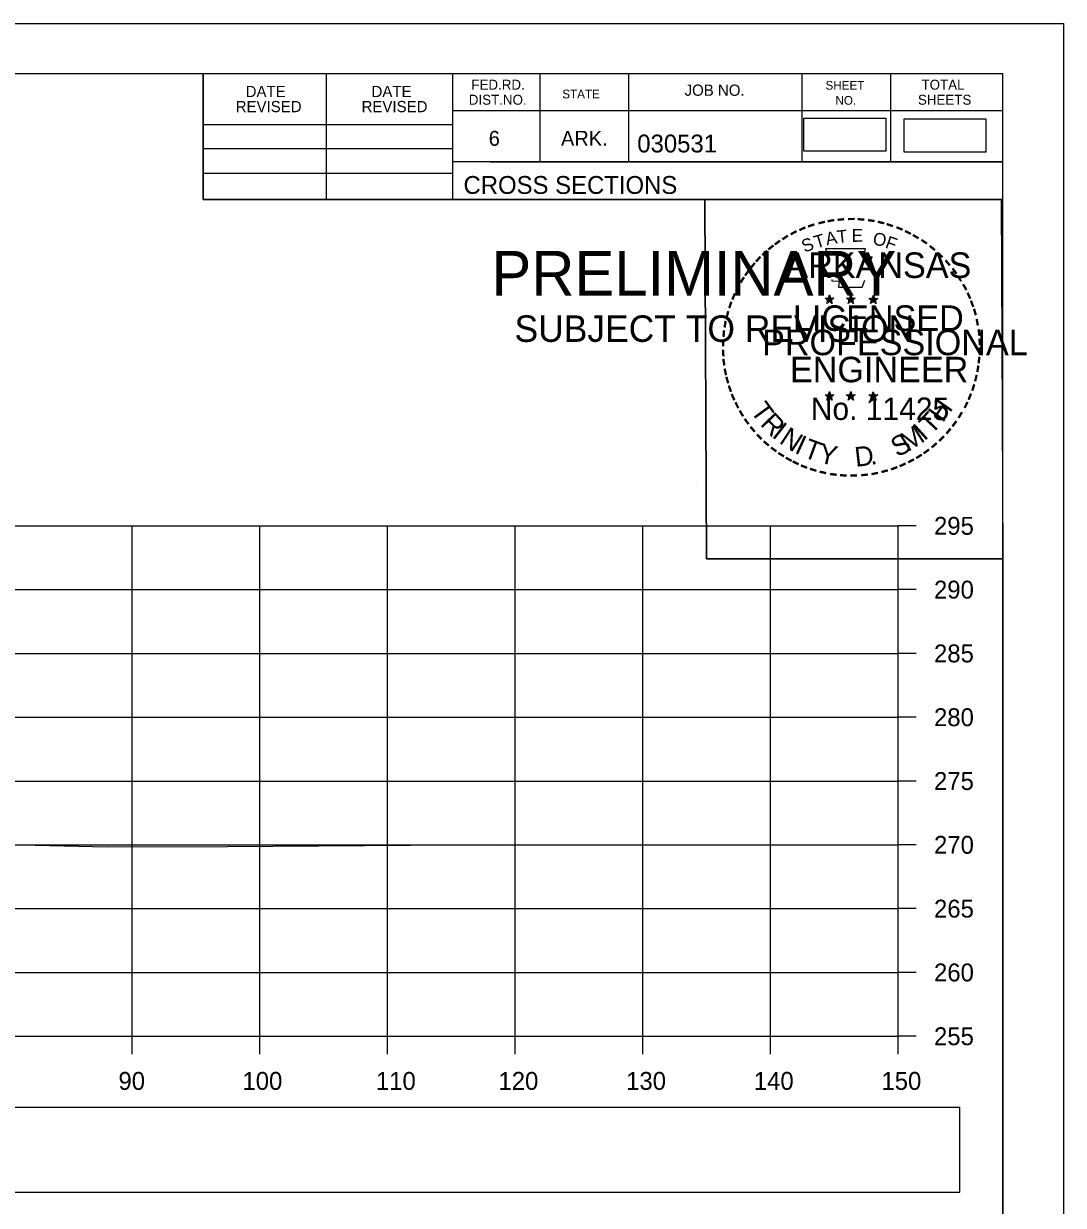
# Model space of a CAD drawing. Extents: x 285 to 4233, y -659 to 3710.
# Drawn here: x 2641 to 2722.4, y 1163.6 to 1256.2 of the extents above; entities that cross this region are included whole.
import ezdxf

# ---------------------------------------------------------------- set-up
doc = ezdxf.new("R2010")
doc.units = 0
for name, color, linetype in [('R_Axis', 7, 'Continuous'), ('R_Axis Annot', 7, 'Continuous'), ('R_Border', 7, 'Continuous'), ('R_Border PE', 7, 'Continuous'), ('R_Border Prem', 7, 'Continuous'), ('R_Exist Surface', 7, 'Continuous'), ('R_Grid', 7, 'Continuous'), ('R_No Plot', 7, 'Continuous')]:
    doc.layers.add(name, color=color, linetype=linetype)

msp = doc.modelspace()

# ---------------------------------------------------------------- linework, layer by layer
at = {"layer": 'R_Axis'}
for p, q in [((2709.501, 1176.842), (2709.501, 1216.842)), ((2710.901, 1216.842), (2709.501, 1216.842)), ((2710.901, 1211.842), (2709.501, 1211.842)), ((2710.901, 1206.842), (2709.501, 1206.842)), ((2710.901, 1201.842), (2709.501, 1201.842)), ((2710.901, 1196.842), (2709.501, 1196.842)), ((2710.901, 1191.842), (2709.501, 1191.842)), ((2710.901, 1186.842), (2709.501, 1186.842)), ((2710.901, 1181.842), (2709.501, 1181.842)), ((2409.501, 1176.842), (2709.501, 1176.842)), ((2649.501, 1175.442), (2649.501, 1176.842)), ((2659.501, 1175.442), (2659.501, 1176.842)), ((2669.501, 1175.442), (2669.501, 1176.842)), ((2679.501, 1175.442), (2679.501, 1176.842)), ((2689.501, 1175.442), (2689.501, 1176.842)), ((2699.501, 1175.442), (2699.501, 1176.842)), ((2709.501, 1175.442), (2709.501, 1176.842)), ((2710.901, 1176.842), (2709.501, 1176.842))]:
    msp.add_line(p, q, dxfattribs=at)
at = {"layer": 'R_Axis Annot'}
for points in [[(2702.085, 1246.216), (2708.544, 1246.216), (2708.544, 1248.774), (2702.085, 1248.774)], [(2709.939, 1246.155), (2716.397, 1246.155), (2716.397, 1248.713), (2709.939, 1248.713)], [(2573.959, 1164.614), (2714.324, 1164.614), (2714.324, 1171.266), (2573.959, 1171.266)]]:
    msp.add_lwpolyline(points, close=True, dxfattribs=at)
at = {"layer": 'R_Border'}
for p, q in [((2401.501, 1252.302), (2717.681, 1252.302)), ((2655.041, 1242.422), (2655.041, 1252.302)), ((2664.721, 1242.422), (2664.721, 1252.302)), ((2674.581, 1252.302), (2674.581, 1242.422)), ((2681.421, 1252.302), (2681.421, 1245.362)), ((2688.361, 1252.302), (2688.361, 1245.362)), ((2701.941, 1252.302), (2701.941, 1245.362)), ((2708.881, 1252.302), (2708.881, 1245.362)), ((2717.681, 1046.842), (2717.681, 1252.302)), ((2717.681, 1249.362), (2674.581, 1249.362)), ((2717.681, 1249.382), (2717.681, 1249.382)), ((2655.041, 1248.282), (2674.581, 1248.282)), ((2655.041, 1246.422), (2674.581, 1246.422)), ((2717.681, 1245.362), (2674.581, 1245.362)), ((2677.541, 1245.362), (2717.681, 1245.362)), ((2655.041, 1244.482), (2674.581, 1244.482)), ((2717.681, 1242.422), (2655.041, 1242.422))]:
    msp.add_line(p, q, dxfattribs=at)
at = {"layer": 'R_Border PE'}
for p, q in [((2703.766, 1234.678), (2704.115, 1234.567)), ((2703.766, 1234.678), (2704.019, 1234.633)), ((2703.766, 1234.678), (2704.003, 1234.556)), ((2703.899, 1234.27), (2704.115, 1234.567)), ((2703.899, 1234.27), (2704.025, 1234.514)), ((2703.899, 1234.27), (2704.113, 1234.487)), ((2704.115, 1234.932), (2704.074, 1234.68)), ((2704.328, 1234.27), (2704.113, 1234.484)), ((2704.115, 1234.567), (2704.115, 1234.932)), ((2704.115, 1234.932), (2704.164, 1234.682)), ((2704.462, 1234.678), (2704.115, 1234.567)), ((2704.328, 1234.27), (2704.115, 1234.567)), ((2704.462, 1234.678), (2704.176, 1234.629)), ((2704.328, 1234.27), (2704.191, 1234.561)), ((2704.462, 1234.678), (2704.258, 1234.576)), ((2705.436, 1234.678), (2705.785, 1234.567)), ((2705.436, 1234.678), (2705.689, 1234.633)), ((2705.436, 1234.678), (2705.673, 1234.556)), ((2705.569, 1234.27), (2705.785, 1234.567)), ((2705.569, 1234.27), (2705.695, 1234.514)), ((2705.569, 1234.27), (2705.783, 1234.487)), ((2705.785, 1234.932), (2705.744, 1234.68)), ((2705.998, 1234.27), (2705.783, 1234.484)), ((2705.785, 1234.567), (2705.785, 1234.932)), ((2705.785, 1234.932), (2705.834, 1234.682)), ((2706.132, 1234.678), (2705.785, 1234.567)), ((2705.998, 1234.27), (2705.785, 1234.567)), ((2706.132, 1234.678), (2705.846, 1234.629)), ((2705.998, 1234.27), (2705.861, 1234.561)), ((2706.132, 1234.678), (2705.928, 1234.576)), ((2707.2, 1234.666), (2707.549, 1234.555)), ((2707.2, 1234.666), (2707.453, 1234.621)), ((2707.2, 1234.666), (2707.437, 1234.544)), ((2707.333, 1234.258), (2707.549, 1234.555)), ((2707.333, 1234.258), (2707.459, 1234.502)), ((2707.333, 1234.258), (2707.547, 1234.475)), ((2707.549, 1234.92), (2707.508, 1234.668)), ((2707.549, 1234.555), (2707.549, 1234.92)), ((2707.549, 1234.92), (2707.598, 1234.67)), ((2707.896, 1234.666), (2707.549, 1234.555)), ((2707.762, 1234.258), (2707.549, 1234.555)), ((2707.896, 1234.666), (2707.61, 1234.617)), ((2707.762, 1234.258), (2707.625, 1234.549)), ((2707.896, 1234.666), (2707.692, 1234.564)), ((2707.762, 1234.258), (2707.547, 1234.472)), ((2703.762, 1227.105), (2704.111, 1226.994)), ((2703.762, 1227.105), (2704.015, 1227.06)), ((2703.762, 1227.105), (2703.999, 1226.983)), ((2704.111, 1227.359), (2704.07, 1227.107)), ((2704.111, 1226.994), (2704.111, 1227.359)), ((2704.111, 1227.359), (2704.16, 1227.109)), ((2704.458, 1227.105), (2704.111, 1226.994)), ((2704.458, 1227.105), (2704.172, 1227.056)), ((2704.458, 1227.105), (2704.254, 1227.003)), ((2705.431, 1227.105), (2705.78, 1226.994)), ((2705.431, 1227.105), (2705.684, 1227.06)), ((2705.431, 1227.105), (2705.668, 1226.983)), ((2705.78, 1227.359), (2705.739, 1227.107)), ((2705.78, 1226.994), (2705.78, 1227.359)), ((2705.78, 1227.359), (2705.829, 1227.109)), ((2706.127, 1227.105), (2705.78, 1226.994)), ((2706.127, 1227.105), (2705.841, 1227.056)), ((2706.127, 1227.105), (2705.923, 1227.003)), ((2707.198, 1227.095), (2707.547, 1226.984)), ((2707.198, 1227.095), (2707.451, 1227.05)), ((2707.198, 1227.095), (2707.435, 1226.973)), ((2707.547, 1227.349), (2707.506, 1227.097)), ((2707.547, 1226.984), (2707.547, 1227.349)), ((2707.547, 1227.349), (2707.596, 1227.099)), ((2707.894, 1227.095), (2707.547, 1226.984)), ((2707.894, 1227.095), (2707.608, 1227.046)), ((2707.894, 1227.095), (2707.69, 1226.993)), ((2703.895, 1226.697), (2704.111, 1226.994)), ((2703.895, 1226.697), (2704.021, 1226.941)), ((2703.895, 1226.697), (2704.109, 1226.914)), ((2704.324, 1226.697), (2704.109, 1226.911)), ((2704.324, 1226.697), (2704.111, 1226.994)), ((2704.324, 1226.697), (2704.187, 1226.988)), ((2705.564, 1226.697), (2705.78, 1226.994)), ((2705.564, 1226.697), (2705.69, 1226.941)), ((2705.564, 1226.697), (2705.778, 1226.914)), ((2705.993, 1226.697), (2705.778, 1226.911)), ((2705.993, 1226.697), (2705.78, 1226.994)), ((2705.993, 1226.697), (2705.856, 1226.988)), ((2707.331, 1226.687), (2707.547, 1226.984)), ((2707.331, 1226.687), (2707.457, 1226.931)), ((2707.331, 1226.687), (2707.545, 1226.904)), ((2707.76, 1226.687), (2707.545, 1226.901)), ((2707.76, 1226.687), (2707.547, 1226.984)), ((2707.76, 1226.687), (2707.623, 1226.978))]:
    msp.add_line(p, q, dxfattribs=at)
for points in [[(2703.807, 1238.556), (2704.076, 1237.729)], [(2707.318, 1237.634), (2707.46, 1237.918), (2706.775, 1237.894), (2706.923, 1238.556), (2703.807, 1238.556)], [(2704.299, 1236.133), (2704.299, 1236.046), (2704.862, 1236.027), (2704.808, 1235.554), (2706.678, 1235.554), (2706.879, 1236.09)], [(2704.115, 1234.932), (2704.328, 1234.27), (2703.766, 1234.678), (2704.462, 1234.678), (2703.899, 1234.27), (2704.115, 1234.932)], [(2705.785, 1234.932), (2705.998, 1234.27), (2705.436, 1234.678), (2706.132, 1234.678), (2705.569, 1234.27), (2705.785, 1234.932)], [(2707.549, 1234.92), (2707.762, 1234.258), (2707.2, 1234.666), (2707.896, 1234.666), (2707.333, 1234.258), (2707.549, 1234.92)], [(2704.111, 1227.359), (2704.324, 1226.697), (2703.762, 1227.105), (2704.458, 1227.105), (2703.895, 1226.697), (2704.111, 1227.359)], [(2705.78, 1227.359), (2705.993, 1226.697), (2705.431, 1227.105), (2706.127, 1227.105), (2705.564, 1226.697), (2705.78, 1227.359)], [(2707.547, 1227.349), (2707.76, 1226.687), (2707.198, 1227.095), (2707.894, 1227.095), (2707.331, 1226.687), (2707.547, 1227.349)]]:
    msp.add_lwpolyline(points, dxfattribs=at)
for centre, radius in [((2704.114, 1234.566), 0.172), ((2704.114, 1234.566), 0.145), ((2704.114, 1234.566), 0.116), ((2704.114, 1234.566), 0.0991), ((2704.114, 1234.566), 0.0747), ((2704.114, 1234.566), 0.0495), ((2704.114, 1234.566), 0.0296), ((2705.784, 1234.566), 0.172), ((2705.784, 1234.566), 0.145), ((2705.784, 1234.566), 0.116), ((2705.784, 1234.566), 0.0991), ((2705.784, 1234.566), 0.0747), ((2705.784, 1234.566), 0.0495), ((2705.784, 1234.566), 0.0296), ((2707.548, 1234.554), 0.172), ((2707.548, 1234.554), 0.145), ((2707.548, 1234.554), 0.116), ((2707.548, 1234.554), 0.0991), ((2707.548, 1234.554), 0.0747), ((2707.548, 1234.554), 0.0495), ((2707.548, 1234.554), 0.0296), ((2704.11, 1226.993), 0.172), ((2704.11, 1226.993), 0.145), ((2704.11, 1226.993), 0.116), ((2704.11, 1226.993), 0.0991), ((2704.11, 1226.993), 0.0747), ((2705.779, 1226.993), 0.172), ((2705.779, 1226.993), 0.145), ((2705.779, 1226.993), 0.116), ((2705.779, 1226.993), 0.0991), ((2705.779, 1226.993), 0.0747), ((2707.546, 1226.983), 0.172), ((2707.546, 1226.983), 0.145), ((2707.546, 1226.983), 0.116), ((2707.546, 1226.983), 0.0991), ((2704.11, 1226.993), 0.0495), ((2704.11, 1226.993), 0.0296), ((2705.779, 1226.993), 0.0495), ((2705.779, 1226.993), 0.0296), ((2707.546, 1226.983), 0.0747), ((2707.546, 1226.983), 0.0495), ((2707.546, 1226.983), 0.0296)]:
    msp.add_circle(centre, radius, dxfattribs=at)
at = {"layer": 'R_Exist Surface'}
msp.add_lwpolyline([(2635.101, 1191.968), (2647.54, 1191.68), (2656.942, 1191.711), (2678.485, 1191.857), (2689.528, 1191.849), (2698.624, 1191.843), (2709.501, 1191.857)], dxfattribs=at)
at = {"layer": 'R_Grid'}
for p, q in [((2409.501, 1216.842), (2709.501, 1216.842)), ((2649.501, 1176.842), (2649.501, 1216.842)), ((2659.501, 1176.842), (2659.501, 1216.842)), ((2669.501, 1176.842), (2669.501, 1216.842)), ((2679.501, 1176.842), (2679.501, 1216.842)), ((2689.501, 1176.842), (2689.501, 1216.842)), ((2699.501, 1176.842), (2699.501, 1216.842)), ((2709.501, 1176.842), (2709.501, 1216.842)), ((2409.501, 1211.842), (2709.501, 1211.842)), ((2409.501, 1206.842), (2709.501, 1206.842)), ((2409.501, 1201.842), (2709.501, 1201.842)), ((2409.501, 1196.842), (2709.501, 1196.842)), ((2409.501, 1191.842), (2709.501, 1191.842)), ((2409.501, 1186.842), (2709.501, 1186.842)), ((2409.501, 1181.842), (2709.501, 1181.842)), ((2409.501, 1176.842), (2709.501, 1176.842))]:
    msp.add_line(p, q, dxfattribs=at)
at = {"layer": 'R_No Plot'}
for p, q in [((2389.1, 1256.197), (2722.433, 1256.197)), ((2693.715, 1219.967), (2693.715, 1219.967))]:
    msp.add_line(p, q, dxfattribs=at)
for points in [[(2389.093, 1256.197), (2722.433, 1256.197), (2722.433, 1042.859), (2389.093, 1042.859)], [(2635.421, 1252.302), (2655.041, 1252.302), (2655.041, 1242.422), (2671.153, 1242.422), (2694.352, 1242.422), (2694.473, 1214.266), (2717.681, 1214.266), (2717.681, 1046.842), (2401.501, 1046.842), (2401.501, 1252.302)], [(2694.352, 1242.422), (2717.56, 1242.422), (2717.681, 1214.266), (2694.473, 1214.266)]]:
    msp.add_lwpolyline(points, close=True, dxfattribs=at)

# ---------------------------------------------------------------- texts
at = {"layer": 'R_Axis Annot'}
for s, p in [('295', (2712.301, 1216.142)), ('290', (2712.301, 1211.142)), ('285', (2712.301, 1206.142)), ('280', (2712.301, 1201.142)), ('275', (2712.301, 1196.142)), ('270', (2712.301, 1191.142)), ('265', (2712.301, 1186.142)), ('260', (2712.301, 1181.142)), ('255', (2712.301, 1176.142)), ('90', (2648.415, 1172.642)), ('100', (2658.128, 1172.642)), ('110', (2668.58, 1172.642)), ('120', (2678.183, 1172.642)), ('130', (2688.183, 1172.642)), ('140', (2698.183, 1172.642)), ('150', (2708.183, 1172.642))]:
    msp.add_text(s, height=1.4, dxfattribs=at).set_placement(p)
at = {"layer": 'R_Border'}
for s, height, p in [('DATE', 0.8792, (2658.379, 1250.439)), ('DATE', 0.8792, (2668.239, 1250.439)), ('FED.RD.', 0.7819, (2676.061, 1251.022)), ('JOB NO.', 0.8792, (2692.761, 1250.542)), ('SHEET', 0.684, (2703.801, 1251.022)), ('TOTAL', 0.7819, (2711.321, 1251.022)), ('DIST.NO.', 0.7819, (2675.861, 1249.842)), ('STATE', 0.684, (2683.181, 1250.342)), ('NO.', 0.684, (2704.581, 1249.842)), ('SHEETS', 0.7819, (2711.041, 1249.842)), ('REVISED', 0.8792, (2657.599, 1249.259)), ('REVISED', 0.8792, (2667.459, 1249.259)), ('6', 1.172, (2677.421, 1246.622)), ('ARK.', 1.1723, (2683.081, 1246.622)), ('030531', 1.4, (2689.057, 1246.102)), ('CROSS SECTIONS', 1.4, (2675.444, 1242.853))]:
    msp.add_text(s, height=height, rotation=360, dxfattribs=at).set_placement(p)
at = {"layer": 'R_Border PE'}
for s, height, rotation, p in [('-', 1.6, 5.89682, (2704.711, 1240.196)), ('-', 1.6, 0.18623, (2705.483, 1240.268)), ('-', 1.6, 357.74304, (2706.206, 1240.255)), ('-', 1.6, 24.30721, (2701.92, 1239.414)), ('-', 1.6, 19.17608, (2702.554, 1239.683)), ('-', 1.6, 13.63015, (2703.304, 1239.924)), ('-', 1.6, 10.21935, (2703.982, 1240.086)), ('T', 1, 6.02276, (2704.75, 1238.982)), ('E', 1, 0.83234, (2705.855, 1239.092)), ('-', 1.6, 352.16172, (2706.95, 1240.199)), ('-', 1.6, 347.20489, (2707.669, 1240.085)), ('-', 1.6, 342.3362, (2708.304, 1239.93)), ('-', 1.6, 337.85509, (2709.039, 1239.707)), ('-', 1.6, 334.12109, (2709.67, 1239.436)), ('-', 1.6, 36.23174, (2700.112, 1238.332)), ('-', 1.6, 34.06357, (2700.69, 1238.727)), ('-', 1.6, 28.79182, (2701.287, 1239.097)), ('S', 1, 21.59401, (2702.161, 1238.234)), ('T', 1, 16.4036, (2703.075, 1238.565)), ('A', 1, 11.21318, (2703.901, 1238.816)), ('O', 1, 350.4515, (2707.459, 1238.882)), ('F', 1, 340.07066, (2708.413, 1238.654)), ('-', 1.6, 329.64089, (2710.249, 1239.153)), ('-', 1.6, 325.86266, (2710.892, 1238.792)), ('-', 1.6, 42.96224, (2699.203, 1237.537)), ('-', 1.6, 38.95066, (2699.636, 1237.954)), ('ARKANSAS', 2, 360, (2700.659, 1236.268)), ('-', 1.6, 320.52971, (2711.502, 1238.366)), ('-', 1.6, 315.57859, (2712.101, 1237.878)), ('-', 1.6, 50.61417, (2698.352, 1236.573)), ('-', 1.6, 48.42305, (2698.755, 1237.059)), ('-', 1.6, 309.87973, (2712.67, 1237.328)), ('-', 1.6, 58.07063, (2697.614, 1235.479)), ('-', 1.6, 54.23247, (2697.939, 1236.006)), ('-', 1.6, 306.65218, (2713.195, 1236.726)), ('-', 1.4, 303.67529, (2713.681, 1236.158)), ('-', 1.6, 62.87135, (2697.301, 1234.865)), ('-', 1.6, 299.66835, (2714, 1235.551)), ('-', 1.6, 67.77427, (2697.042, 1234.254)), ('DWB', 0.01, 360, (2704.102, 1234.561)), ('DWB', 0.01, 360, (2705.772, 1234.561)), ('DWB', 0.01, 360, (2707.536, 1234.551)), ('-', 1.6, 294.66279, (2714.324, 1234.939)), ('-', 1.6, 290.57283, (2714.581, 1234.362)), ('-', 1.6, 75.46096, (2696.626, 1232.91)), ('-', 1.6, 72.39447, (2696.823, 1233.624)), ('LICENSED', 2, 360, (2701.257, 1232.119)), ('-', 1.6, 285.12326, (2714.815, 1233.782)), ('-', 1.6, 81.20126, (2696.494, 1232.197)), ('-', 1.6, 280.54934, (2715.015, 1233.04)), ('-', 1.6, 85.18634, (2696.418, 1231.506)), ('PROFESSIONAL', 2, 360, (2698.833, 1230.215)), ('-', 1.6, 276.59616, (2715.177, 1232.272)), ('-', 1.6, 89.06224, (2696.393, 1230.805)), ('-', 1.6, 274.33011, (2715.237, 1231.55)), ('-', 1.6, 269.94067, (2715.271, 1230.918)), ('-', 1.6, 94.19588, (2696.428, 1230.08)), ('-', 1.6, 98.94793, (2696.5, 1229.413)), ('ENGINEER', 2, 360, (2701.02, 1228.09)), ('-', 1.6, 263.5172, (2715.252, 1230.252)), ('-', 1.6, 101.71495, (2696.635, 1228.68)), ('-', 1.6, 260.99529, (2715.181, 1229.598)), ('-', 1.6, 105.45785, (2696.797, 1228.085)), ('-', 1.6, 255.7626, (2715.071, 1228.92)), ('-', 1.6, 109.08742, (2697.012, 1227.454)), ('-', 1.6, 114.06432, (2697.266, 1226.858)), ('-', 1.6, 247.88866, (2714.667, 1227.527)), ('-', 1.6, 252.86809, (2714.89, 1228.2)), ('-', 1.6, 115.72885, (2697.571, 1226.24)), ('T', 1.54, 306.04056, (2697.87, 1225.832)), ('No. 11425', 1.757, 360, (2702.648, 1225.139)), ('DWB', 0.01, 360, (2704.098, 1226.989)), ('DWB', 0.01, 360, (2705.767, 1226.989)), ('DWB', 0.01, 360, (2707.534, 1226.979)), ('H', 1.54, 54.60883, (2712.99, 1224.867)), ('-', 1.6, 244.61971, (2714.405, 1226.898)), ('-', 1.6, 120.44712, (2697.928, 1225.654)), ('-', 1.6, 125.89344, (2698.331, 1225.093)), ('R', 1.54, 314.00497, (2698.633, 1224.784)), ('T', 1.54, 46.64442, (2712.101, 1223.925)), ('-', 1.6, 239.07125, (2714.011, 1226.146)), ('-', 1.6, 130.71812, (2698.793, 1224.541)), ('I', 1.54, 321.96938, (2699.533, 1223.852)), ('N', 1.54, 326.50021, (2700.1, 1223.38)), ('M', 1.54, 32.65632, (2710.255, 1222.599)), ('I', 1.54, 42.11359, (2711.539, 1223.446)), ('-', 1.6, 231.25377, (2713.179, 1224.927)), ('-', 1.6, 233.84524, (2713.609, 1225.493)), ('-', 1.6, 134.22381, (2699.31, 1223.996)), ('-', 1.6, 138.93382, (2699.835, 1223.532)), ('I', 1.54, 335.36034, (2701.309, 1222.594)), ('T', 1.54, 339.89117, (2701.97, 1222.267)), ('S', 1.54, 26.9312, (2709.416, 1222.194)), ('-', 1.6, 221.08509, (2712.178, 1223.854)), ('-', 1.6, 225.76533, (2712.7, 1224.363)), ('-', 1.6, 144.64634, (2700.391, 1223.126)), ('-', 1.6, 148.08978, (2700.952, 1222.755)), ('Y', 1.54, 347.85558, (2703.187, 1221.822)), ('D', 1.54, 6.39691, (2706.171, 1221.463)), ('-', 1.6, 212.24909, (2711.095, 1222.995)), ('-', 1.6, 215.73633, (2711.629, 1223.382)), ('-', 1.6, 151.57039, (2701.531, 1222.43)), ('-', 1.6, 154.60019, (2702.053, 1222.183)), ('-', 1.6, 158.56121, (2702.677, 1221.929)), ('.', 1.54, 13.76417, (2707.363, 1221.59)), ('-', 1.6, 200.71842, (2709.294, 1222.057)), ('-', 1.6, 204.25161, (2709.913, 1222.33)), ('-', 1.6, 207.35684, (2710.537, 1222.649)), ('-', 1.6, 162.79826, (2703.364, 1221.716)), ('-', 1.6, 167.55551, (2704.079, 1221.552)), ('-', 1.6, 173.11546, (2704.851, 1221.442)), ('-', 1.6, 176.51827, (2705.599, 1221.389)), ('-', 1.6, 181.59176, (2706.343, 1221.408)), ('-', 1.6, 185.81666, (2707.152, 1221.484)), ('-', 1.6, 191.28576, (2707.888, 1221.616)), ('-', 1.6, 195.47429, (2708.617, 1221.815))]:
    msp.add_text(s, height=height, rotation=rotation, dxfattribs=at).set_placement(p)
at = {"layer": 'R_Border Prem'}
for s, height, p in [('PRELIMINARY', 3.5, (2677.632, 1234.886)), ('DWB', 0.01, (2678.379, 1236.735)), ('SUBJECT TO REVISION', 2.07511, (2679.441, 1231.257))]:
    msp.add_text(s, height=height, rotation=360, dxfattribs=at).set_placement(p)

doc.saveas('drawing.dxf')
